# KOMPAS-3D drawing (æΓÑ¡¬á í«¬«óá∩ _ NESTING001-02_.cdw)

Views: Вид 1, Снизу
Referenced files in \\Smallatom\скворечник\: Боковая стенка.m3d, Стенка боковая _ NESTING001-02.cdw
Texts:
  NESTING001-02
  Стенка боковая
  Лит-Масса-Масштаб
  Материал-Предприятие
  Title Specification
  Body Specification ( left align )
  Body Specificaton ( centered )
  Поз.
  Кол.
  Приме-
  чание
  Таблица спецификации
  Демьянова Л.В.
  NESTING001-02-
  КЮТ СО РАН
Dimensions and other numbers on the sheet: 140; 10; 110; 70; 250; 60; 4,2; 4 отв.; 6; 1:2; 1; 0,47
